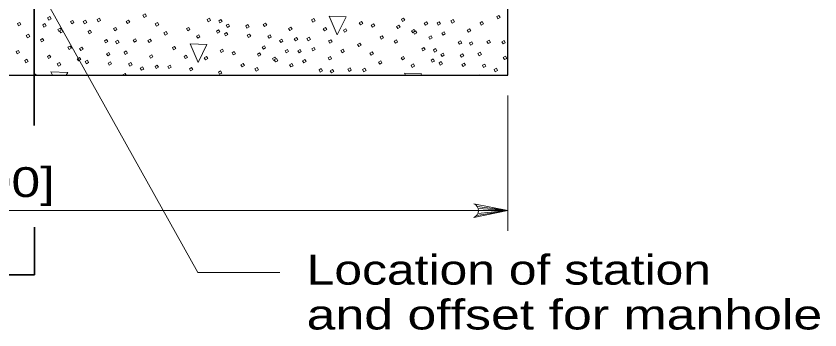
# Model space of a CAD drawing. Extents: x 1083.1 to 1117.1, y 697.4 to 741.4.
# Drawn here: x 1099.373 to 1103.58, y 728.174 to 729.815 of the extents above; entities that cross this region are included whole.
import ezdxf

# ---------------------------------------------------------------- set-up
doc = ezdxf.new("R2010")
doc.units = 0
doc.header["$LTSCALE"] = 0.062
doc.layers.add('1', color=7, linetype='Continuous', lineweight=13)

msp = doc.modelspace()

# ---------------------------------------------------------------- linework, layer by layer
at = {"layer": '1', "lineweight": 35}
for p, q in [((1099.46825, 730.24133), (1099.46825, 729.24258)), ((1099.46892, 728.46133), (1099.46892, 728.71075)), ((1099.46892, 728.46133), (1098.88167, 728.46133))]:
    msp.add_line(p, q, dxfattribs=at)
at = {"layer": '1', "lineweight": 25}
for p, q in [((1101.94625, 729.50575), (1101.94625, 730.00642)), ((1096.99167, 729.50575), (1101.94625, 729.50575))]:
    msp.add_line(p, q, dxfattribs=at)
at = {"layer": '1'}
for p, q in [((1099.59783, 729.735), (1099.59175, 729.74592)), ((1101.44975, 729.72767), (1101.44367, 729.73858)), ((1100.72125, 729.58258), (1100.71517, 729.59342)), ((1099.55508, 729.52467), (1099.56333, 729.50575)), ((1099.93425, 729.50575), (1099.93267, 729.5085)), ((1101.407, 729.51733), (1101.412, 729.50575)), ((1101.94625, 729.39975), (1101.94625, 728.69175)), ((1101.78417, 728.773), (1101.94625, 728.79775)), ((1101.786, 728.82017), (1101.94625, 728.79775)), ((1101.79025, 728.78333), (1101.94625, 728.79775)), ((1101.79142, 728.80908), (1101.94625, 728.79775)), ((1101.79308, 728.79775), (1101.94625, 728.79775))]:
    msp.add_line(p, q, dxfattribs=at)
for points in [[(1099.46533, 730.01242), (1100.32467, 728.47442), (1100.75425, 728.47442)], [(1099.59175, 729.74592), (1099.60358, 729.75258), (1099.60683, 729.74692)], [(1101.44367, 729.73858), (1101.4555, 729.74525), (1101.45867, 729.73958)], [(1100.71517, 729.59342), (1100.727, 729.60017), (1100.73025, 729.5945)], [(1099.46358, 729.50575), (1099.47458, 729.512), (1099.47817, 729.50575)], [(1099.63583, 729.50575), (1099.64325, 729.52092), (1099.55508, 729.52467)], [(1099.93267, 729.5085), (1099.9445, 729.51517), (1099.94983, 729.50575)], [(1100.20258, 729.50575), (1100.20408, 729.50658), (1100.20458, 729.50575)], [(1100.77833, 729.50575), (1100.77967, 729.50642), (1100.78008, 729.50575)], [(1101.49125, 729.50575), (1101.49508, 729.51358), (1101.407, 729.51733)], [(1101.79267, 729.50575), (1101.79642, 729.50783), (1101.79767, 729.50575)], [(1101.76925, 728.76233), (1101.94625, 728.79775), (1101.76925, 728.83317)], [(1098.68133, 728.79775), (1099.98333, 728.79775), (1101.94625, 728.79775)]]:
    msp.add_lwpolyline(points, dxfattribs=at)
for points in [[(1099.53783, 729.806), (1099.54967, 729.81275), (1099.556, 729.8015), (1099.54417, 729.79483)], [(1099.72458, 729.78683), (1099.73642, 729.7935), (1099.74275, 729.78225), (1099.73092, 729.77558)], [(1099.79733, 729.79742), (1099.80917, 729.80417), (1099.8155, 729.79292), (1099.80367, 729.78617)], [(1099.94958, 729.78733), (1099.96142, 729.79408), (1099.96775, 729.78283), (1099.95592, 729.77608)], [(1100.037, 729.81983), (1100.04883, 729.82658), (1100.05517, 729.81533), (1100.04333, 729.80858)], [(1100.37292, 729.79733), (1100.38475, 729.804), (1100.39108, 729.79275), (1100.37925, 729.78608)], [(1100.43392, 729.79117), (1100.44575, 729.79792), (1100.45208, 729.78667), (1100.44025, 729.77992)], [(1100.91975, 729.7955), (1100.93158, 729.80225), (1100.93792, 729.791), (1100.92608, 729.78425)], [(1101.01208, 729.81492), (1101.05458, 729.7175), (1101.10017, 729.81117)], [(1101.38967, 729.79875), (1101.4015, 729.80542), (1101.40783, 729.79417), (1101.396, 729.7875)], [(1101.64925, 729.79017), (1101.66108, 729.79683), (1101.66742, 729.78558), (1101.65558, 729.77892)], [(1101.88883, 729.8125), (1101.90067, 729.81925), (1101.90708, 729.808), (1101.89517, 729.80125)], [(1099.38025, 729.77583), (1099.39208, 729.7825), (1099.3985, 729.77125), (1099.38658, 729.76458)], [(1099.51267, 729.76917), (1099.5245, 729.77592), (1099.53083, 729.76467), (1099.519, 729.75792)], [(1099.65792, 729.7865), (1099.66975, 729.79317), (1099.67608, 729.78192), (1099.66425, 729.77525)], [(1099.88308, 729.74967), (1099.89492, 729.75642), (1099.90125, 729.74517), (1099.88942, 729.73842)], [(1100.10192, 729.77458), (1100.11375, 729.78125), (1100.12008, 729.77), (1100.10825, 729.76333)], [(1100.26533, 729.74975), (1100.27717, 729.7565), (1100.2835, 729.74525), (1100.27167, 729.7385)], [(1100.47283, 729.76717), (1100.48467, 729.77392), (1100.491, 729.76267), (1100.47917, 729.75592)], [(1100.57492, 729.76383), (1100.58675, 729.77058), (1100.59308, 729.75933), (1100.58125, 729.75258)], [(1100.66683, 729.77167), (1100.67867, 729.77842), (1100.685, 729.76717), (1100.67317, 729.76042)], [(1100.7995, 729.75133), (1100.81133, 729.75808), (1100.81775, 729.74683), (1100.80583, 729.74008)], [(1100.98083, 729.74917), (1100.99275, 729.75583), (1100.99908, 729.74458), (1100.98725, 729.73792)], [(1101.16967, 729.78092), (1101.1815, 729.78767), (1101.18783, 729.77642), (1101.176, 729.76967)], [(1101.23217, 729.7685), (1101.244, 729.77517), (1101.25033, 729.764), (1101.2385, 729.75725)], [(1101.3645, 729.76183), (1101.37633, 729.76858), (1101.38267, 729.75733), (1101.37083, 729.75067)], [(1101.50975, 729.77917), (1101.52158, 729.78583), (1101.52792, 729.77458), (1101.51608, 729.76792)], [(1101.57642, 729.7795), (1101.58833, 729.78617), (1101.59467, 729.77492), (1101.58283, 729.76825)], [(1101.8015, 729.78), (1101.81333, 729.78675), (1101.81967, 729.7755), (1101.80783, 729.76875)], [(1099.42642, 729.7135), (1099.43825, 729.72025), (1099.44458, 729.709), (1099.43275, 729.70225)], [(1099.60083, 729.739), (1099.61267, 729.74575), (1099.619, 729.7345), (1099.60717, 729.72775)], [(1099.74967, 729.73417), (1099.7615, 729.74092), (1099.76783, 729.72967), (1099.756, 729.72292)], [(1100.14683, 729.72767), (1100.15875, 729.73433), (1100.16508, 729.72308), (1100.15325, 729.71642)], [(1100.31733, 729.71058), (1100.32917, 729.71733), (1100.3355, 729.70608), (1100.32367, 729.69933)], [(1100.42167, 729.73742), (1100.4335, 729.74408), (1100.43992, 729.73283), (1100.428, 729.72617)], [(1100.46342, 729.72283), (1100.47525, 729.72958), (1100.48158, 729.71833), (1100.46975, 729.71158)], [(1100.58333, 729.715), (1100.59517, 729.72167), (1100.6015, 729.71042), (1100.58967, 729.70375)], [(1100.69058, 729.71033), (1100.7025, 729.71708), (1100.70883, 729.70583), (1100.697, 729.69908)], [(1101.08667, 729.74242), (1101.0985, 729.74917), (1101.10483, 729.73792), (1101.093, 729.73117)], [(1101.27825, 729.70617), (1101.29008, 729.71292), (1101.29642, 729.70167), (1101.28458, 729.695)], [(1101.45275, 729.73167), (1101.46458, 729.73842), (1101.47092, 729.72717), (1101.45908, 729.72042)], [(1101.53325, 729.70567), (1101.54508, 729.71242), (1101.55142, 729.70117), (1101.53958, 729.69442)], [(1101.60158, 729.72683), (1101.61342, 729.73358), (1101.61975, 729.72233), (1101.60792, 729.71558)], [(1101.73492, 729.74233), (1101.74675, 729.74908), (1101.75308, 729.73783), (1101.74125, 729.73108)], [(1099.50025, 729.69158), (1099.51208, 729.69825), (1099.51842, 729.68708), (1099.50658, 729.68033)], [(1099.83542, 729.68642), (1099.84725, 729.69317), (1099.85358, 729.68192), (1099.84175, 729.67517)], [(1099.89408, 729.682), (1099.90592, 729.68875), (1099.91225, 729.6775), (1099.90042, 729.67075)], [(1099.986, 729.68983), (1099.99783, 729.6965), (1100.00417, 729.68525), (1099.99233, 729.67858)], [(1100.06358, 729.68808), (1100.07542, 729.69483), (1100.08175, 729.68358), (1100.06992, 729.67683)], [(1100.28358, 729.66975), (1100.32608, 729.57233), (1100.37167, 729.66608)], [(1100.75183, 729.68808), (1100.76367, 729.69483), (1100.77, 729.68358), (1100.75817, 729.67683)], [(1100.82892, 729.69725), (1100.84083, 729.704), (1100.84717, 729.69275), (1100.83525, 729.686)], [(1100.89567, 729.69758), (1100.9075, 729.70433), (1100.91383, 729.69308), (1100.902, 729.68633)], [(1101.00858, 729.68517), (1101.02042, 729.69192), (1101.02675, 729.68067), (1101.01492, 729.67392)], [(1101.16033, 729.66742), (1101.17225, 729.67408), (1101.17858, 729.66283), (1101.16667, 729.65617)], [(1101.35208, 729.68425), (1101.364, 729.69092), (1101.37033, 729.67975), (1101.3585, 729.673)], [(1101.68725, 729.67908), (1101.69908, 729.68583), (1101.70542, 729.67458), (1101.69358, 729.66783)], [(1101.746, 729.67467), (1101.75783, 729.68142), (1101.76417, 729.67017), (1101.75233, 729.66342)], [(1101.83792, 729.6825), (1101.84975, 729.68917), (1101.85608, 729.67792), (1101.84425, 729.67125)], [(1101.9155, 729.68075), (1101.92733, 729.6875), (1101.93367, 729.67625), (1101.92183, 729.6695)], [(1099.37342, 729.62942), (1099.38525, 729.63617), (1099.39158, 729.62492), (1099.37975, 729.61817)], [(1099.64442, 729.65217), (1099.65625, 729.65892), (1099.66258, 729.64767), (1099.65075, 729.64092)], [(1099.70542, 729.64608), (1099.71725, 729.65275), (1099.72358, 729.64158), (1099.71175, 729.63483)], [(1099.84642, 729.61875), (1099.85825, 729.62542), (1099.86458, 729.61425), (1099.85275, 729.6075)], [(1099.93833, 729.62658), (1099.95017, 729.63325), (1099.9565, 729.622), (1099.94467, 729.61533)], [(1100.19125, 729.65042), (1100.20308, 729.65708), (1100.20942, 729.64583), (1100.19758, 729.63917)], [(1100.44117, 729.63583), (1100.45308, 729.6425), (1100.45942, 729.63125), (1100.4475, 729.62458)], [(1100.50367, 729.62333), (1100.5155, 729.63008), (1100.52183, 729.61883), (1100.51, 729.61208)], [(1100.66117, 729.65358), (1100.673, 729.66033), (1100.67933, 729.64908), (1100.6675, 729.64233)], [(1100.78125, 729.634), (1100.79308, 729.64075), (1100.79942, 729.6295), (1100.78758, 729.62275)], [(1100.848, 729.63433), (1100.85983, 729.64108), (1100.86617, 729.62983), (1100.85433, 729.62308)], [(1100.92075, 729.645), (1100.93258, 729.65175), (1100.93892, 729.6405), (1100.92708, 729.63375)], [(1101.073, 729.63492), (1101.08483, 729.64158), (1101.09117, 729.63033), (1101.07933, 729.62367)], [(1101.22533, 729.62208), (1101.23717, 729.62883), (1101.2435, 729.61758), (1101.23167, 729.61083)], [(1101.49625, 729.64483), (1101.50817, 729.65158), (1101.5145, 729.64033), (1101.50258, 729.63358)], [(1101.55725, 729.63875), (1101.56908, 729.64542), (1101.57542, 729.63425), (1101.56358, 729.6275)], [(1101.79025, 729.61925), (1101.80208, 729.62592), (1101.80842, 729.61467), (1101.79658, 729.608)], [(1099.41842, 729.5825), (1099.43025, 729.58925), (1099.43658, 729.578), (1099.42475, 729.57125)], [(1099.53683, 729.60467), (1099.54867, 729.61133), (1099.555, 729.60017), (1099.54317, 729.59342)], [(1099.69317, 729.59225), (1099.70508, 729.599), (1099.71142, 729.58775), (1099.6995, 729.581)], [(1099.73492, 729.57775), (1099.74675, 729.58442), (1099.75308, 729.57317), (1099.74125, 729.5665)], [(1100.071, 729.60625), (1100.08292, 729.613), (1100.08925, 729.60175), (1100.07733, 729.595)], [(1100.25242, 729.604), (1100.26425, 729.61075), (1100.27058, 729.5995), (1100.25875, 729.59275)], [(1100.35817, 729.59733), (1100.37, 729.604), (1100.37633, 729.59275), (1100.3645, 729.58608)], [(1100.636, 729.61675), (1100.64783, 729.6235), (1100.65425, 729.61225), (1100.64233, 729.6055)], [(1100.72425, 729.58658), (1100.73608, 729.59325), (1100.74242, 729.58208), (1100.73058, 729.57533)], [(1100.87308, 729.58175), (1100.88492, 729.5885), (1100.89125, 729.57725), (1100.87942, 729.5705)], [(1101.00642, 729.59725), (1101.01825, 729.60392), (1101.02458, 729.59267), (1101.01275, 729.586)], [(1101.38875, 729.59733), (1101.40058, 729.604), (1101.40692, 729.59283), (1101.39508, 729.58608)], [(1101.54508, 729.58492), (1101.55692, 729.59167), (1101.56325, 729.58042), (1101.55142, 729.57367)], [(1101.59625, 729.61475), (1101.60808, 729.62142), (1101.61442, 729.61017), (1101.60258, 729.6035)], [(1101.69833, 729.61142), (1101.71017, 729.61817), (1101.7165, 729.60692), (1101.70467, 729.60017)], [(1101.92292, 729.59892), (1101.93475, 729.60567), (1101.94108, 729.59442), (1101.92925, 729.58767)], [(1099.58883, 729.56542), (1099.60067, 729.57217), (1099.607, 729.56092), (1099.59517, 729.55417)], [(1099.85483, 729.56983), (1099.86667, 729.57658), (1099.873, 729.56533), (1099.86117, 729.55858)], [(1099.96217, 729.56525), (1099.974, 729.572), (1099.98033, 729.56075), (1099.9685, 729.554)], [(1100.02333, 729.543), (1100.03517, 729.54967), (1100.04158, 729.5385), (1100.02967, 729.53175)], [(1100.10042, 729.55217), (1100.11233, 729.55883), (1100.11867, 729.54767), (1100.10675, 729.54092)], [(1100.16717, 729.5525), (1100.179, 729.55917), (1100.18533, 729.548), (1100.1735, 729.54125)], [(1100.28008, 729.54008), (1100.29192, 729.54675), (1100.29825, 729.5355), (1100.28642, 729.52883)], [(1100.54975, 729.56108), (1100.56158, 729.56783), (1100.56792, 729.55658), (1100.55608, 729.54983)], [(1100.62367, 729.53908), (1100.6355, 729.54583), (1100.64183, 729.53458), (1100.63, 729.52783)], [(1100.80475, 729.5605), (1100.81658, 729.56725), (1100.82292, 729.556), (1100.81108, 729.54933)], [(1101.10942, 729.53733), (1101.12125, 729.54408), (1101.12758, 729.53283), (1101.11575, 729.52608)], [(1101.187, 729.53567), (1101.19883, 729.54233), (1101.20517, 729.53117), (1101.19333, 729.52442)], [(1101.27025, 729.57517), (1101.28208, 729.58192), (1101.28842, 729.57067), (1101.27658, 729.56392)], [(1101.44075, 729.55817), (1101.45258, 729.56483), (1101.45892, 729.55358), (1101.44708, 729.54692)], [(1101.58683, 729.57042), (1101.59867, 729.57708), (1101.605, 729.56583), (1101.59317, 729.55917)], [(1101.70675, 729.5625), (1101.71858, 729.56925), (1101.72492, 729.558), (1101.71308, 729.55125)], [(1101.814, 729.55792), (1101.82583, 729.56467), (1101.83217, 729.55342), (1101.82033, 729.54667)], [(1101.87525, 729.53567), (1101.88708, 729.54233), (1101.89342, 729.53117), (1101.88158, 729.52442)], [(1100.43192, 729.52225), (1100.44375, 729.529), (1100.45008, 729.51775), (1100.43825, 729.511)], [(1100.95875, 729.53392), (1100.97058, 729.54067), (1100.97692, 729.52942), (1100.96508, 729.52275)], [(1101.0175, 729.52958), (1101.02933, 729.53625), (1101.03567, 729.525), (1101.02383, 729.51833)]]:
    msp.add_lwpolyline(points, close=True, dxfattribs=at)
msp.add_arc((1101.75497, 728.7978), 0.0382, 292.08605, 67.91218, dxfattribs=at)

# ---------------------------------------------------------------- texts
for s, width, p in [('5\'-4" [1600]', 1.3, (1098.20558, 728.86917)), ('Location of station', 1.25, (1100.894, 728.41092)), ('and offset for manhole', 1.3, (1100.894, 728.17625))]:
    msp.add_text(s, height=0.156, dxfattribs=dict(at, width=width)).set_placement(p)

doc.saveas('drawing.dxf')
